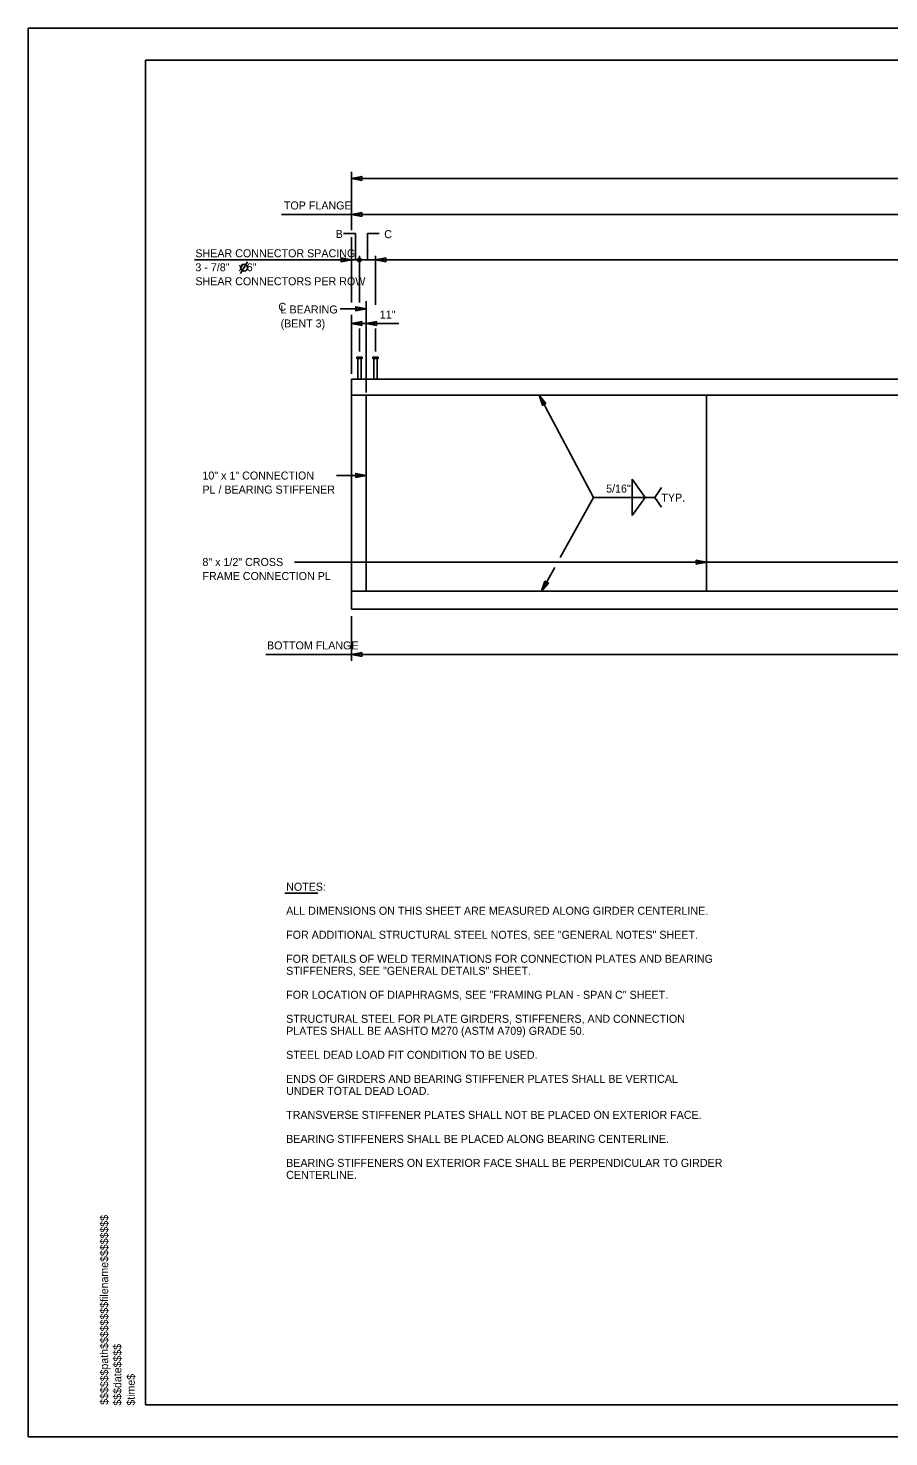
# Model space of a CAD drawing. Extents: x -305 to -161, y -187 to -99.
# Drawn here: x -305.2 to -251.4, y -187.5 to -99.5 of the extents above; entities that cross this region are included whole.
import ezdxf

# ---------------------------------------------------------------- set-up
doc = ezdxf.new("R2010")
doc.units = 0
for name, color, linetype in [('BR_AUTO DIMENSION', 7, 'Continuous'), ('BR_BORDER LINES', 7, 'Continuous'), ('BR_CENTER LINES', 7, 'Continuous'), ('BR_STRUCTURAL STEEL', 7, 'Continuous'), ('BR_TEXT', 7, 'Continuous'), ('Default', 7, 'Continuous'), ('Level 31', 7, 'Continuous'), ('RD_SHT_ID', 7, 'Continuous')]:
    doc.layers.add(name, color=color, linetype=linetype)

msp = doc.modelspace()

# ---------------------------------------------------------------- linework, layer by layer
at = {"layer": 'BR_AUTO DIMENSION'}
for p, q in [((-284.971, -112.109), (-284.971, -108.463)), ((-284.971, -108.876), (-176.721, -108.876)), ((-284.971, -111.134), (-289.341, -111.134)), ((-284.971, -111.134), (-176.721, -111.134)), ((-284.971, -116.618), (-284.971, -112.544)), ((-284.971, -113.971), (-294.788, -113.971)), ((-283.471, -113.971), (-284.971, -113.971)), ((-284.471, -116.618), (-284.471, -113.71)), ((-283.471, -116.774), (-283.471, -113.71)), ((-178.221, -113.971), (-283.471, -113.971)), ((-284.055, -117.022), (-285.674, -117.022)), ((-284.971, -121.093), (-284.971, -117.389)), ((-284.971, -117.946), (-282.012, -117.946)), ((-284.471, -119.685), (-284.471, -118.256)), ((-283.471, -119.685), (-283.471, -118.256)), ((-269.841, -128.801), (-273.229, -122.412)), ((-284.055, -127.431), (-285.907, -127.431)), ((-267.425, -127.667), (-267.425, -129.935)), ((-267.425, -127.667), (-266.619, -128.801)), ((-266.016, -128.801), (-265.583, -128.194)), ((-269.841, -128.801), (-271.919, -132.559)), ((-269.841, -128.801), (-266.016, -128.801)), ((-267.425, -129.935), (-266.619, -128.801)), ((-266.016, -128.801), (-265.583, -129.408)), ((-198.921, -132.851), (-288.526, -132.851)), ((-272.263, -133.182), (-273.082, -134.662)), ((-284.971, -136.215), (-284.971, -139.018)), ((-284.971, -138.617), (-290.319, -138.617)), ((-284.971, -138.617), (-176.721, -138.617)), ((-289.143, -153.536), (-287.066, -153.536))]:
    msp.add_line(p, q, dxfattribs=at)
for points in [[(-284.321, -109.001), (-284.971, -108.876), (-284.321, -108.751)], [(-284.321, -111.259), (-284.971, -111.134), (-284.321, -111.009)], [(-285.621, -114.096), (-284.971, -113.971), (-285.621, -113.846)], [(-282.821, -114.096), (-283.471, -113.971), (-282.821, -113.846)], [(-284.705, -117.147), (-284.055, -117.022), (-284.705, -116.897)], [(-284.321, -117.821), (-284.971, -117.946), (-284.321, -118.071)], [(-283.405, -118.071), (-284.055, -117.946), (-283.405, -117.821)], [(-272.814, -122.928), (-273.229, -122.412), (-273.035, -123.045)], [(-284.705, -127.556), (-284.055, -127.431), (-284.705, -127.306)], [(-263.421, -132.976), (-262.771, -132.851), (-263.421, -132.726)], [(-272.877, -134.033), (-273.082, -134.662), (-272.658, -134.154)], [(-284.321, -138.742), (-284.971, -138.617), (-284.321, -138.492)]]:
    msp.add_lwpolyline(points, close=True, dxfattribs=at)
for points in [[(-284.721, -113.971), (-284.721, -112.325), (-285.462, -112.325)], [(-283.971, -113.971), (-283.971, -112.325), (-283.231, -112.325)]]:
    msp.add_lwpolyline(points, dxfattribs=at)
msp.add_circle((-284.471, -113.971), 0.111, dxfattribs=at)
at = {"layer": 'BR_BORDER LINES'}
for p, q in [((-163.178, -101.489), (-297.843, -101.489)), ((-297.843, -185.489), (-297.843, -101.489)), ((-297.843, -185.489), (-163.178, -185.489))]:
    msp.add_line(p, q, dxfattribs=at)
at = {"layer": 'BR_CENTER LINES'}
msp.add_line((-284.055, -116.535), (-284.055, -122.256), dxfattribs=at)
at = {"layer": 'BR_STRUCTURAL STEEL'}
for p, q in [((-284.971, -121.412), (-176.721, -121.412)), ((-284.971, -121.412), (-284.971, -122.412)), ((-284.971, -122.412), (-176.721, -122.412)), ((-284.971, -122.412), (-284.971, -134.662)), ((-284.055, -122.412), (-284.055, -134.662)), ((-262.771, -122.412), (-262.771, -134.662)), ((-284.971, -134.662), (-176.721, -134.662)), ((-284.971, -134.662), (-284.971, -135.787)), ((-284.971, -135.787), (-176.721, -135.787))]:
    msp.add_line(p, q, dxfattribs=at)
at = {"layer": 'BR_TEXT'}
msp.add_line((-291.896, -114.817), (-291.476, -114.089), dxfattribs=at)
msp.add_circle((-291.686, -114.453), 0.22, dxfattribs=at)
at = {"layer": 'Default'}
for p, q in [((-284.643, -120.037), (-284.643, -120.131)), ((-284.643, -120.037), (-284.3, -120.037)), ((-284.643, -120.131), (-284.3, -120.131)), ((-284.581, -120.131), (-284.581, -121.412)), ((-284.362, -120.131), (-284.362, -121.412)), ((-284.3, -120.037), (-284.3, -120.131)), ((-283.643, -120.037), (-283.643, -120.131)), ((-283.643, -120.037), (-283.3, -120.037)), ((-283.643, -120.131), (-283.3, -120.131)), ((-283.581, -120.131), (-283.581, -121.412)), ((-283.362, -120.131), (-283.362, -121.412)), ((-283.3, -120.037), (-283.3, -120.131))]:
    msp.add_line(p, q, dxfattribs=at)
at = {"layer": 'Level 31'}
msp.add_lwpolyline([(-305.176, -187.489), (-161.176, -187.489), (-161.176, -99.489), (-305.176, -99.489)], close=True, dxfattribs=at)

# ---------------------------------------------------------------- texts
at = {"layer": 'BR_AUTO DIMENSION'}
for s, p in [('TOP FLANGE', (-289.193, -110.815)), ('B', (-285.957, -112.593)), ('C', (-282.92, -112.609)), ('11"', (-283.198, -117.627)), ('5/16"', (-269.053, -128.501)), ('TYP.', (-265.599, -129.067)), ('BOTTOM FLANGE', (-290.248, -138.298)), ('NOTES:', (-289.051, -153.375)), ('ALL DIMENSIONS ON THIS SHEET ARE MEASURED ALONG GIRDER CENTERLINE.', (-289.051, -154.875)), ('FOR ADDITIONAL STRUCTURAL STEEL NOTES, SEE "GENERAL NOTES" SHEET.', (-289.051, -156.375)), ('FOR DETAILS OF WELD TERMINATIONS FOR CONNECTION PLATES AND BEARING ', (-289.051, -157.875)), ('STIFFENERS, SEE "GENERAL DETAILS" SHEET.', (-289.051, -158.625)), ('FOR LOCATION OF DIAPHRAGMS, SEE "FRAMING PLAN - SPAN C" SHEET.', (-289.051, -160.125)), ('STRUCTURAL STEEL FOR PLATE GIRDERS, STIFFENERS, AND CONNECTION ', (-289.051, -161.625)), ('PLATES SHALL BE AASHTO M270 (ASTM A709) GRADE 50.', (-289.051, -162.375)), ('STEEL DEAD LOAD FIT CONDITION TO BE USED.', (-289.051, -163.875)), ('ENDS OF GIRDERS AND BEARING STIFFENER PLATES SHALL BE VERTICAL', (-289.051, -165.375)), ('UNDER TOTAL DEAD LOAD.', (-289.051, -166.125)), ('TRANSVERSE STIFFENER PLATES SHALL NOT BE PLACED ON EXTERIOR FACE.', (-289.051, -167.625)), ('BEARING STIFFENERS SHALL BE PLACED ALONG BEARING CENTERLINE.', (-289.051, -169.125)), ('BEARING STIFFENERS ON EXTERIOR FACE SHALL BE PERPENDICULAR TO GIRDER', (-289.051, -170.625)), ('CENTERLINE.', (-289.051, -171.375))]:
    msp.add_text(s, height=0.5, rotation=360, dxfattribs=at).set_placement(p)
at = {"layer": 'BR_TEXT'}
for s, p in [('SHEAR CONNECTOR SPACING', (-294.724, -113.801)), ('3 - 7/8"   x 6" ', (-294.724, -114.676)), ('SHEAR CONNECTORS PER ROW', (-294.724, -115.551)), ('C', (-289.535, -117.145)), ('L BEARING', (-289.399, -117.311)), ('(BENT 3)', (-289.399, -118.186)), ('10" x 1" CONNECTION ', (-294.284, -127.688)), ('PL / BEARING STIFFENER', (-294.284, -128.563)), ('8" x 1/2" CROSS ', (-294.284, -133.088)), ('FRAME CONNECTION PL', (-294.284, -133.963))]:
    msp.add_text(s, height=0.5, rotation=360, dxfattribs=at).set_placement(p)
at = {"layer": 'RD_SHT_ID'}
for s, height, p in [('$$$$$$path$$$$$$$$filename$$$$$$$$', 0.49387, (-300.176, -185.489)), ('$$$date$$$$', 0.49387, (-299.353, -185.542)), ('$time$', 0.4939, (-298.509, -185.542))]:
    msp.add_text(s, height=height, rotation=90, dxfattribs=at).set_placement(p)

doc.saveas('drawing.dxf')
